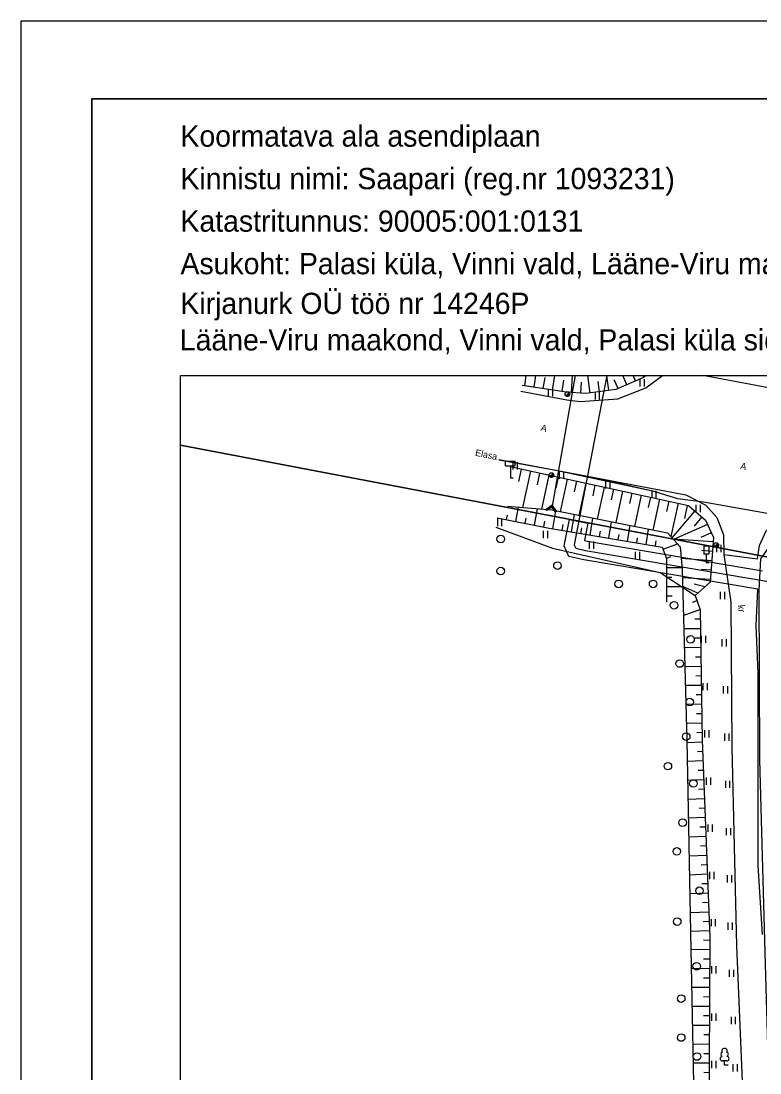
# Model space of a CAD drawing. Extents: x 657488 to 657645, y 6569018 to 6569240.
# Drawn here: x 657487.9 to 657566.2, y 6569129 to 6569240.4 of the extents above; entities that cross this region are included whole.
import ezdxf

# ---------------------------------------------------------------- set-up
doc = ezdxf.new("R2010")
doc.units = 0
for name, color, linetype in [('HALJASTUS', 7, 'Continuous'), ('KASUTUSALA', 7, 'Continuous'), ('LIIKLUS', 7, 'Continuous'), ('PIIR', 7, 'Continuous'), ('POST', 7, 'Continuous'), ('PR_SIDE', 7, 'Continuous'), ('PUU', 7, 'Continuous'), ('RELJEEF', 7, 'Continuous'), ('SITRASS', 7, 'Continuous'), ('TEE', 7, 'Continuous'), ('TRUUP', 7, 'Continuous'), ('VORMISTUS', 7, 'Continuous')]:
    doc.layers.add(name, color=color, linetype=linetype)

msp = doc.modelspace()

# ---------------------------------------------------------------- linework, layer by layer
at = {"layer": 'HALJASTUS'}
for p, q in [((657553.45, 6569202.46), (657553.45, 6569201.69)), ((657553.91, 6569202.46), (657553.91, 6569201.69)), ((657543.76, 6569201.42), (657543.76, 6569200.66)), ((657544.22, 6569201.42), (657544.22, 6569200.66)), ((657548.72, 6569201.07), (657548.72, 6569200.31)), ((657549.17, 6569201.07), (657549.17, 6569200.31)), ((657540.02, 6569193.66), (657540.02, 6569192.9)), ((657540.48, 6569193.66), (657540.48, 6569192.9)), ((657544.92, 6569192.66), (657544.92, 6569191.9)), ((657545.38, 6569192.66), (657545.38, 6569191.9)), ((657549.82, 6569191.66), (657549.82, 6569190.9)), ((657550.28, 6569191.66), (657550.28, 6569190.9)), ((657554.72, 6569190.65), (657554.72, 6569189.89)), ((657555.17, 6569190.65), (657555.17, 6569189.89)), ((657559.4, 6569189.15), (657559.4, 6569188.39)), ((657559.85, 6569189.15), (657559.85, 6569188.39)), ((657538.38, 6569187.66), (657538.38, 6569186.9)), ((657538.83, 6569187.66), (657538.83, 6569186.9)), ((657543.21, 6569186.4), (657543.21, 6569185.64)), ((657543.67, 6569186.4), (657543.67, 6569185.64)), ((657548.08, 6569185.26), (657548.08, 6569184.5)), ((657548.54, 6569185.26), (657548.54, 6569184.5)), ((657552.96, 6569184.18), (657552.96, 6569183.42)), ((657553.42, 6569184.18), (657553.42, 6569183.42)), ((657561.57, 6569184.92), (657561.57, 6569184.16)), ((657562.03, 6569184.92), (657562.03, 6569184.16)), ((657561.97, 6569179.94), (657561.97, 6569179.18)), ((657562.43, 6569179.94), (657562.43, 6569179.18)), ((657559.97, 6569175.3), (657559.97, 6569174.54)), ((657560.43, 6569175.3), (657560.43, 6569174.54)), ((657562.15, 6569174.95), (657562.15, 6569174.18)), ((657562.61, 6569174.95), (657562.61, 6569174.18)), ((657560.14, 6569170.3), (657560.14, 6569169.54)), ((657560.6, 6569170.3), (657560.6, 6569169.54)), ((657562.28, 6569169.95), (657562.28, 6569169.19)), ((657562.74, 6569169.95), (657562.74, 6569169.19)), ((657560.32, 6569165.3), (657560.32, 6569164.54)), ((657560.77, 6569165.3), (657560.77, 6569164.54)), ((657562.41, 6569164.95), (657562.41, 6569164.19)), ((657562.87, 6569164.95), (657562.87, 6569164.19)), ((657560.49, 6569160.31), (657560.49, 6569159.54)), ((657560.94, 6569160.31), (657560.94, 6569159.54)), ((657562.52, 6569159.95), (657562.52, 6569159.19)), ((657562.97, 6569159.95), (657562.97, 6569159.19)), ((657560.66, 6569155.31), (657560.66, 6569154.55)), ((657561.11, 6569155.31), (657561.11, 6569154.55)), ((657562.61, 6569154.95), (657562.61, 6569154.19)), ((657563.06, 6569154.95), (657563.06, 6569154.19)), ((657560.83, 6569150.31), (657560.83, 6569149.55)), ((657561.28, 6569150.31), (657561.28, 6569149.55)), ((657562.7, 6569149.95), (657562.7, 6569149.19)), ((657563.15, 6569149.95), (657563.15, 6569149.19)), ((657561, 6569145.31), (657561, 6569144.55)), ((657561.45, 6569145.31), (657561.45, 6569144.55)), ((657562.78, 6569144.95), (657562.78, 6569144.19)), ((657563.24, 6569144.95), (657563.24, 6569144.19)), ((657561.05, 6569140.32), (657561.05, 6569139.55)), ((657561.5, 6569140.32), (657561.5, 6569139.55)), ((657562.93, 6569139.95), (657562.93, 6569139.19)), ((657563.39, 6569139.95), (657563.39, 6569139.19)), ((657561.05, 6569135.32), (657561.05, 6569134.55)), ((657561.5, 6569135.32), (657561.5, 6569134.55)), ((657563.12, 6569134.96), (657563.12, 6569134.2)), ((657563.57, 6569134.96), (657563.57, 6569134.2)), ((657561.05, 6569130.32), (657561.05, 6569129.55)), ((657561.5, 6569130.32), (657561.5, 6569129.55)), ((657563.3, 6569129.96), (657563.3, 6569129.2)), ((657563.76, 6569129.96), (657563.76, 6569129.2))]:
    msp.add_line(p, q, dxfattribs=at)
msp.add_lwpolyline([(657538.21, 6569186.78), (657544.22, 6569184.58), (657555.63, 6569181.98), (657559.31, 6569179.56)], dxfattribs=at)
for centre in [(657538.73, 6569185.54), (657544.74, 6569182.72), (657538.73, 6569182.15), (657551.22, 6569180.78), (657554.87, 6569180.78), (657557.08, 6569178.53), (657558.83, 6569174.91), (657557.69, 6569172.36), (657558.75, 6569168.28), (657558.37, 6569164.63), (657556.43, 6569161.5), (657559.13, 6569159.67), (657557.99, 6569155.52), (657557.38, 6569152.48), (657559.78, 6569148.32), (657557.42, 6569145.05), (657559.48, 6569140.33), (657557.84, 6569136.9), (657557.84, 6569132.78), (657559.52, 6569130.77)]:
    msp.add_circle(centre, 0.4, dxfattribs=at)
at = {"layer": 'KASUTUSALA'}
msp.add_lwpolyline([(657566.45, 6569143.68), (657566, 6569150.98), (657566, 6569171.38), (657565.79, 6569176.4), (657565.97, 6569180.22), (657547.53, 6569183.35), (657545.96, 6569183.69), (657545.46, 6569184.82), (657546, 6569187.61), (657547.96, 6569187.23), (657547.6, 6569185.38), (657547.91, 6569185.32), (657566.45, 6569182.17)], dxfattribs=at)
at = {"layer": 'LIIKLUS'}
for p, q in [((657539.25, 6569193.78), (657540.25, 6569193.78)), ((657539.25, 6569193.28), (657539.25, 6569193.78)), ((657539.25, 6569193.28), (657540.25, 6569193.28)), ((657539.75, 6569193.28), (657539.75, 6569192.03)), ((657540.25, 6569193.28), (657540.25, 6569193.78)), ((657539.75, 6569192.03), (657540.05, 6569192.03)), ((657560.25, 6569184.78), (657560.25, 6569183.93)), ((657560.75, 6569184.78), (657560.25, 6569184.78)), ((657560.75, 6569183.93), (657560.25, 6569183.93)), ((657560.5, 6569183.93), (657560.5, 6569183.03)), ((657560.75, 6569184.78), (657560.75, 6569183.93)), ((657560.75, 6569183.03), (657560.5, 6569183.03))]:
    msp.add_line(p, q, dxfattribs=at)
at = {"layer": 'PIIR'}
for p, q in [((657628.56, 6569171.87), (657504.81, 6569195.46)), ((657504.81, 6569195.46), (657628.56, 6569171.87))]:
    msp.add_line(p, q, dxfattribs=at)
for points in [[(657628.56, 6569189.83), (657571.83, 6569200.65), (657569.16, 6569201.16), (657560.13, 6569202.86)], [(657571.76, 6569202.86), (657571.83, 6569200.65), (657569.16, 6569201.16), (657560.13, 6569202.86)]]:
    msp.add_lwpolyline(points, dxfattribs=at)
at = {"layer": 'POST'}
for p, q in [((657545.62, 6569200.7), (657545.97, 6569201.05)), ((657543.92, 6569192.12), (657544.28, 6569192.48)), ((657561.38, 6569184.73), (657561.73, 6569185.08))]:
    msp.add_line(p, q, dxfattribs=at)
for centre in [(657545.8, 6569200.88), (657544.1, 6569192.3), (657561.55, 6569184.9)]:
    msp.add_circle(centre, 0.25, dxfattribs=at)
for centre, radius, start, end in [((657545.8, 6569200.88), 0.225, 224.8541, 45.0356), ((657545.8, 6569200.88), 0.2, 224.8427, 45.047), ((657545.8, 6569200.88), 0.175, 224.8281, 45.0616), ((657545.8, 6569200.88), 0.15, 224.8087, 45.081), ((657545.8, 6569200.88), 0.125, 224.7814, 45.1083), ((657545.8, 6569200.88), 0.1, 224.7406, 45.1491), ((657545.8, 6569200.88), 0.075, 224.6725, 45.2172), ((657545.8, 6569200.88), 0.05, 224.5363, 45.3534), ((657545.8, 6569200.88), 0.025, 224.1278, 45.7619), ((657544.1, 6569192.3), 0.225, 224.8541, 45.0356), ((657544.1, 6569192.3), 0.2, 224.8427, 45.047), ((657544.1, 6569192.3), 0.175, 224.8281, 45.0616), ((657544.1, 6569192.3), 0.15, 224.8087, 45.081), ((657544.1, 6569192.3), 0.125, 224.7814, 45.1083), ((657544.1, 6569192.3), 0.1, 224.7406, 45.1491), ((657544.1, 6569192.3), 0.075, 224.6725, 45.2172), ((657544.1, 6569192.3), 0.05, 224.5363, 45.3534), ((657544.1, 6569192.3), 0.025, 224.1278, 45.7619), ((657561.55, 6569184.9), 0.225, 224.8541, 45.0356), ((657561.55, 6569184.9), 0.2, 224.8427, 45.047), ((657561.55, 6569184.9), 0.175, 224.8281, 45.0616), ((657561.55, 6569184.9), 0.15, 224.8087, 45.081), ((657561.55, 6569184.9), 0.125, 224.7814, 45.1083), ((657561.55, 6569184.9), 0.1, 224.7406, 45.1491), ((657561.55, 6569184.9), 0.075, 224.6725, 45.2172), ((657561.55, 6569184.9), 0.05, 224.5363, 45.3534), ((657561.55, 6569184.9), 0.025, 224.1278, 45.7619)]:
    msp.add_arc(centre, radius, start, end, dxfattribs=at)
at = {"layer": 'PR_SIDE'}
msp.add_lwpolyline([(657549.98, 6569202.86), (657546.5, 6569184.94), (657546.67, 6569184.56), (657547.72, 6569184.33), (657567.09, 6569181.05), (657587.18, 6569177.64)], dxfattribs=at)
at = {"layer": 'PUU'}
for p, q in [((657562.67, 6569130.31), (657562.19, 6569130.31)), ((657562.43, 6569129.84), (657562.43, 6569130.31)), ((657562.81, 6569129.84), (657562.43, 6569129.84))]:
    msp.add_line(p, q, dxfattribs=at)
for centre, radius, start, end in [((657562.43, 6569131.36), 0.277, 332.5799, 207.4201), ((657562.19, 6569130.55), 0.238, 90.0016, 269.3953), ((657562.26, 6569131.01), 0.233, 109.0217, 253.1415), ((657562.6, 6569131.01), 0.233, 286.8508, 70.9859), ((657562.67, 6569130.55), 0.238, 270.6047, 89.9984)]:
    msp.add_arc(centre, radius, start, end, dxfattribs=at)
at = {"layer": 'RELJEEF'}
for p, q in [((657541.27, 6569201.75), (657541.44, 6569202.86)), ((657542.26, 6569201.6), (657542.45, 6569202.86)), ((657544.23, 6569201.29), (657544.47, 6569202.86)), ((657546.21, 6569201.04), (657546.34, 6569202.86)), ((657548.21, 6569200.99), (657547.96, 6569202.86)), ((657550.19, 6569201.26), (657549.98, 6569202.86)), ((657552.08, 6569201.85), (657551.65, 6569202.86)), ((657553, 6569202.25), (657552.74, 6569202.86)), ((657553.91, 6569202.66), (657553.76, 6569202.86)), ((657543.24, 6569201.45), (657543.43, 6569202.63)), ((657545.22, 6569201.14), (657545.41, 6569202.34)), ((657547.21, 6569200.97), (657547.29, 6569202.15)), ((657549.2, 6569201.12), (657549.05, 6569202.2)), ((657551.16, 6569201.46), (657550.76, 6569202.39)), ((657540.9, 6569192.94), (657540.61, 6569191.61)), ((657541.87, 6569192.73), (657541.03, 6569188.87)), ((657542.85, 6569192.51), (657542.58, 6569191.27)), ((657543.83, 6569192.3), (657543.04, 6569188.7)), ((657544.81, 6569192.09), (657544.55, 6569190.93)), ((657545.78, 6569191.87), (657545.03, 6569188.43)), ((657546.76, 6569191.66), (657546.51, 6569190.52)), ((657547.74, 6569191.45), (657546.99, 6569188.04)), ((657548.71, 6569191.23), (657548.47, 6569190.11)), ((657549.69, 6569191.02), (657548.96, 6569187.65)), ((657550.67, 6569190.81), (657550.42, 6569189.69)), ((657551.64, 6569190.6), (657550.92, 6569187.27)), ((657552.62, 6569190.38), (657552.38, 6569189.28)), ((657553.6, 6569190.17), (657552.88, 6569186.88)), ((657554.58, 6569189.96), (657554.34, 6569188.86)), ((657555.55, 6569189.74), (657554.84, 6569186.49)), ((657556.53, 6569189.53), (657556.29, 6569188.45)), ((657540.33, 6569187.39), (657540.63, 6569188.9)), ((657542.3, 6569187), (657542.64, 6569188.73)), ((657544.26, 6569186.62), (657544.58, 6569188.52)), ((657557.51, 6569189.32), (657556.74, 6569185.8)), ((657559.28, 6569188.52), (657556.85, 6569185.68)), ((657558.48, 6569189.1), (657558.18, 6569187.7)), ((657539.35, 6569187.59), (657539.45, 6569188.05)), ((657541.31, 6569187.2), (657541.42, 6569187.74)), ((657543.28, 6569186.81), (657543.4, 6569187.42)), ((657546.23, 6569186.29), (657546.54, 6569188.13)), ((657548.2, 6569185.96), (657548.5, 6569187.74)), ((657550.18, 6569185.63), (657550.47, 6569187.36)), ((657560.04, 6569187.87), (657559.2, 6569186.89)), ((657545.25, 6569186.46), (657545.35, 6569187.08)), ((657547.22, 6569186.13), (657547.32, 6569186.73)), ((657549.19, 6569185.8), (657549.29, 6569186.38)), ((657552.15, 6569185.3), (657552.43, 6569186.97)), ((657554.12, 6569184.97), (657554.39, 6569186.58)), ((657560.63, 6569187.09), (657557.02, 6569185.49)), ((657561.03, 6569186.18), (657559.93, 6569185.69)), ((657551.16, 6569185.47), (657551.26, 6569186.03)), ((657553.14, 6569185.14), (657553.23, 6569185.68)), ((657555.11, 6569184.81), (657555.2, 6569185.33)), ((657555.93, 6569184.45), (657557.44, 6569185.02)), ((657561.21, 6569185.23), (657556.99, 6569185.52)), ((657561.14, 6569184.23), (657560.01, 6569184.31)), ((657556.29, 6569183.51), (657556.79, 6569183.7)), ((657561.07, 6569183.23), (657557.85, 6569183.46)), ((657556.3, 6569182.51), (657557.94, 6569182.51)), ((657561, 6569182.23), (657559.98, 6569182.31)), ((657556.3, 6569181.51), (657556.86, 6569181.51)), ((657560.93, 6569181.24), (657557.98, 6569181.44)), ((657560.36, 6569180.49), (657559.22, 6569180.75)), ((657556.3, 6569180.51), (657558, 6569180.51)), ((657556.3, 6569179.51), (657556.88, 6569179.51)), ((657559.61, 6569179.82), (657558, 6569180.51)), ((657559.51, 6569178.99), (657559.02, 6569178.82)), ((657559.83, 6569178.05), (657558.08, 6569177.44)), ((657559.85, 6569177.05), (657559.27, 6569177.04)), ((657559.87, 6569176.05), (657558.12, 6569176.02)), ((657559.89, 6569175.05), (657559.31, 6569175.04)), ((657559.9, 6569174.05), (657558.17, 6569174.02)), ((657559.92, 6569173.05), (657559.35, 6569173.04)), ((657559.94, 6569172.05), (657558.22, 6569172.02)), ((657559.96, 6569171.05), (657559.39, 6569171.04)), ((657559.97, 6569170.05), (657558.28, 6569170.02)), ((657559.99, 6569169.05), (657559.43, 6569169.04)), ((657560.01, 6569168.05), (657558.33, 6569168.02)), ((657560.02, 6569167.05), (657559.47, 6569167.04)), ((657560.04, 6569166.05), (657558.38, 6569166.02)), ((657560.06, 6569165.05), (657559.51, 6569165.04)), ((657560.08, 6569164.05), (657558.43, 6569163.98)), ((657560.12, 6569163.05), (657559.56, 6569163.03)), ((657560.15, 6569162.05), (657558.47, 6569161.98)), ((657560.19, 6569161.05), (657559.63, 6569161.03)), ((657560.23, 6569160.05), (657558.51, 6569159.98)), ((657560.27, 6569159.05), (657559.69, 6569159.03)), ((657560.31, 6569158.05), (657558.56, 6569157.98)), ((657560.39, 6569156.05), (657558.6, 6569155.98)), ((657560.35, 6569157.05), (657559.76, 6569157.03)), ((657560.43, 6569155.05), (657559.82, 6569155.03)), ((657560.46, 6569154.06), (657558.64, 6569153.98)), ((657560.5, 6569153.06), (657559.89, 6569153.03)), ((657560.54, 6569152.06), (657558.68, 6569151.98)), ((657560.58, 6569151.06), (657559.95, 6569151.03)), ((657560.62, 6569150.06), (657558.72, 6569149.98)), ((657560.66, 6569149.06), (657560.02, 6569149.03)), ((657560.7, 6569148.06), (657558.76, 6569147.99)), ((657560.77, 6569146.06), (657558.8, 6569145.99)), ((657560.74, 6569147.06), (657560.08, 6569147.04)), ((657560.81, 6569145.06), (657560.15, 6569145.04)), ((657560.85, 6569144.06), (657558.84, 6569143.99)), ((657560.88, 6569143.06), (657560.2, 6569143.07)), ((657560.87, 6569142.06), (657558.88, 6569142.08)), ((657560.86, 6569141.06), (657560.21, 6569141.07)), ((657560.86, 6569140.06), (657558.92, 6569140.08)), ((657560.85, 6569139.06), (657560.21, 6569139.07)), ((657560.85, 6569138.06), (657558.96, 6569138.08)), ((657560.83, 6569136.06), (657559, 6569136.07)), ((657560.84, 6569137.06), (657560.22, 6569137.07)), ((657560.83, 6569135.06), (657560.22, 6569135.07)), ((657560.82, 6569134.06), (657559.04, 6569134.07)), ((657560.82, 6569133.06), (657560.23, 6569133.07)), ((657560.81, 6569132.06), (657559.07, 6569132.07)), ((657560.8, 6569131.06), (657560.23, 6569131.07)), ((657560.8, 6569130.06), (657559.11, 6569130.07)), ((657560.79, 6569129.06), (657560.24, 6569129.07))]:
    msp.add_line(p, q, dxfattribs=at)
for points in [[(657554.17, 6569202.86), (657553.86, 6569202.62), (657550.91, 6569201.35), (657547.76, 6569200.93), (657545.65, 6569201.07), (657541, 6569201.79)], [(657539.92, 6569193.16), (657544.71, 6569192.11), (657558.63, 6569189.07), (657560.43, 6569187.53), (657561.25, 6569185.69), (657560.91, 6569180.98), (657559.31, 6569179.56), (657559.84, 6569178.03), (657560.07, 6569164.24), (657560.88, 6569143.4), (657560.76, 6569123.21), (657561.22, 6569100.2), (657562.13, 6569085.45), (657561.78, 6569078.09), (657561.18, 6569075.32), (657560.11, 6569075.32), (657559.46, 6569078.1)], [(657539.44, 6569189), (657544.13, 6569188.61), (657556.39, 6569186.18), (657557.73, 6569184.7), (657557.95, 6569182.35), (657558.43, 6569164.25), (657558.84, 6569143.94), (657559.72, 6569099.61), (657560.54, 6569077.79)], [(657538.37, 6569187.78), (657543.86, 6569186.69), (657555.84, 6569184.69), (657556.3, 6569183.49), (657556.3, 6569178.84)]]:
    msp.add_lwpolyline(points, dxfattribs=at)
at = {"layer": 'SITRASS'}
for points in [[(657538.53, 6569193.96), (657540.07, 6569193.68), (657548.47, 6569192.07), (657554.79, 6569190.63), (657557.45, 6569189.84), (657560.21, 6569189.46), (657567.76, 6569188.12), (657573.68, 6569187.05), (657580.3, 6569186.08), (657583.99, 6569185.45), (657587.1, 6569183.47), (657591.99, 6569180.17)], [(657538.53, 6569193.93), (657544.74, 6569192.8), (657554.79, 6569190.63), (657557.45, 6569189.84), (657560.21, 6569189.46), (657567.76, 6569188.12), (657573.68, 6569187.05), (657580.3, 6569186.08), (657583.99, 6569185.45)]]:
    msp.add_lwpolyline(points, dxfattribs=at)
at = {"layer": 'TEE'}
for points in [[(657540.87, 6569201.17), (657545.74, 6569200.27), (657547.15, 6569200.1), (657551.13, 6569200.38), (657554.11, 6569201.53), (657555.85, 6569202.86)], [(657539.77, 6569193.69), (657544.74, 6569192.8), (657558.33, 6569190.21), (657560.45, 6569189.13), (657561.62, 6569187.82), (657562.32, 6569185.97), (657562.36, 6569183.9), (657565.91, 6569183.43), (657566.13, 6569184.86), (657566.85, 6569186.39), (657568.45, 6569187.46), (657570.88, 6569187.83), (657580.95, 6569185.94), (657591.06, 6569183.97), (657604.9, 6569181.45)], [(657554.4, 6569062), (657559.25, 6569063.03), (657564.82, 6569064.83), (657569.62, 6569065.37), (657570.35, 6569067.36), (657568.53, 6569067.26), (657568.59, 6569069.38), (657568.42, 6569074.3), (657568.5, 6569085.24), (657567.81, 6569100.86), (657567.28, 6569122.21), (657566.73, 6569141.77), (657566.17, 6569162.21), (657566.11, 6569180.12), (657566.26, 6569183.44), (657568.59, 6569186.68), (657570.88, 6569187.83)], [(657562.36, 6569183.9), (657563.08, 6569178.84), (657563.2, 6569163.5), (657563.71, 6569142.47), (657564.54, 6569122.23), (657565.13, 6569100.99), (657565.66, 6569086.51), (657565.85, 6569081.53), (657565.66, 6569078.18), (657565, 6569074.55), (657563.44, 6569070.87), (657560.75, 6569067.79), (657557.83, 6569066.14)]]:
    msp.add_lwpolyline(points, dxfattribs=at)
at = {"layer": 'TRUUP'}
for p, q in [((657546.63, 6569202.86), (657544.17, 6569189.02)), ((657544.19, 6569189.12), (657543.55, 6569188.67)), ((657543.63, 6569188.55), (657543.55, 6569188.67)), ((657543.58, 6569188.64), (657543.57, 6569188.68)), ((657544.17, 6569189.02), (657543.59, 6569188.61)), ((657543.61, 6569188.59), (657543.59, 6569188.7)), ((657543.64, 6569188.56), (657543.61, 6569188.71)), ((657544.15, 6569188.92), (657543.63, 6569188.55)), ((657543.66, 6569188.57), (657543.64, 6569188.73)), ((657543.68, 6569188.59), (657543.66, 6569188.75)), ((657543.71, 6569188.6), (657543.68, 6569188.76)), ((657543.73, 6569188.62), (657543.71, 6569188.78)), ((657543.75, 6569188.64), (657543.73, 6569188.79)), ((657543.77, 6569188.65), (657543.75, 6569188.81)), ((657543.8, 6569188.67), (657543.77, 6569188.83)), ((657543.82, 6569188.68), (657543.8, 6569188.84)), ((657543.84, 6569188.7), (657543.82, 6569188.86)), ((657543.87, 6569188.72), (657543.84, 6569188.87)), ((657543.89, 6569188.73), (657543.87, 6569188.89)), ((657543.91, 6569188.75), (657543.89, 6569188.91)), ((657543.94, 6569188.76), (657543.91, 6569188.92)), ((657543.96, 6569188.78), (657543.94, 6569188.94)), ((657543.98, 6569188.8), (657543.96, 6569188.95)), ((657544, 6569188.81), (657543.98, 6569188.97)), ((657544.03, 6569188.83), (657544, 6569188.99)), ((657544.05, 6569188.84), (657544.03, 6569189)), ((657544.07, 6569188.86), (657544.05, 6569189.02)), ((657544.1, 6569188.88), (657544.07, 6569189.03)), ((657544.12, 6569188.89), (657544.1, 6569189.05)), ((657544.14, 6569188.91), (657544.12, 6569189.07)), ((657544.17, 6569188.9), (657544.14, 6569189.08)), ((657544.52, 6569188.4), (657544.15, 6569188.92)), ((657544.2, 6569188.85), (657544.17, 6569189.1)), ((657544.58, 6569188.44), (657544.17, 6569189.02)), ((657544.63, 6569188.48), (657544.19, 6569189.12)), ((657544.23, 6569188.8), (657544.19, 6569189.11)), ((657544.26, 6569188.76), (657544.22, 6569189.07)), ((657544.3, 6569188.71), (657544.25, 6569189.03)), ((657544.33, 6569188.67), (657544.28, 6569188.98)), ((657544.36, 6569188.62), (657544.31, 6569188.94)), ((657544.39, 6569188.58), (657544.35, 6569188.89)), ((657544.42, 6569188.53), (657544.38, 6569188.84)), ((657544.46, 6569188.49), (657544.41, 6569188.8)), ((657544.49, 6569188.44), (657544.44, 6569188.75)), ((657544.52, 6569188.4), (657544.47, 6569188.71)), ((657544.54, 6569188.41), (657544.51, 6569188.66)), ((657544.52, 6569188.4), (657544.63, 6569188.48)), ((657544.56, 6569188.43), (657544.54, 6569188.62)), ((657544.59, 6569188.44), (657544.57, 6569188.57)), ((657544.61, 6569188.46), (657544.6, 6569188.53))]:
    msp.add_line(p, q, dxfattribs=at)
at = {"layer": 'VORMISTUS'}
for points in [[(657487.94, 6569240.36), (657645.44, 6569240.36), (657645.44, 6569017.61), (657487.94, 6569017.61)], [(657495.44, 6569025.86), (657637.94, 6569025.86), (657637.94, 6569232.11), (657495.44, 6569232.11)], [(657495.44, 6569232.11), (657637.94, 6569232.11), (657637.94, 6569025.86), (657495.44, 6569025.86)], [(657628.56, 6569045.36), (657504.81, 6569045.36), (657504.81, 6569202.86), (657628.56, 6569202.86)]]:
    msp.add_lwpolyline(points, close=True, dxfattribs=at)

# ---------------------------------------------------------------- texts
at = {"layer": 'SITRASS'}
msp.add_text('Elasa', height=0.7, rotation=348.6164, dxfattribs=at).set_placement((657535.99, 6569194.36))
at = {"layer": 'TEE'}
for s, rotation, p in [('A', 345.6474, (657542.92, 6569197.02)), ('A', 346.2256, (657564.06, 6569192.98)), ('kr', 275.7167, (657563.84, 6569178.53))]:
    msp.add_text(s, height=0.7, rotation=rotation, dxfattribs=at).set_placement(p)
at = {"layer": 'VORMISTUS'}
for s, p in [('Koormatava ala asendiplaan', (657504.82, 6569227.06)), ('Kinnistu nimi: Saapari (reg.nr 1093231)', (657504.82, 6569222.56)), ('Katastritunnus: 90005:001:0131', (657504.82, 6569218.06)), ('Asukoht: Palasi küla, Vinni vald, Lääne-Viru maakond', (657504.82, 6569213.56))]:
    msp.add_text(s, height=2.25, dxfattribs=at).set_placement(p)
for s, p in [('Kirjanurk OÜ töö nr 14246P', (657504.81, 6569209.35)), ('Lääne-Viru maakond, Vinni vald, Palasi küla siderajatis', (657504.75, 6569205.49))]:
    msp.add_text(s, height=2.25, rotation=360, dxfattribs=at).set_placement(p)

doc.saveas('drawing.dxf')
